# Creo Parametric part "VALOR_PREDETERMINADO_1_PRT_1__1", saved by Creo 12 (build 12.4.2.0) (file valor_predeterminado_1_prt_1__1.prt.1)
Units: Custom; MM, KILOGRAM, SECS

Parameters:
  PTC_WM_ITERATION = "0"
  PTC_WM_VERSION = "-.0"
  PTC_WM_LIFECYCLE_STATE = "In Work"
  PTC_WM_LIFECYCLE = "MO_CADDocument"
  PTC_WM_CREATED_BY = "Maximilian Roepper (Z0017RMS: MO)"
  PTC_WM_CREATED_ON = "18-Sep-26 11:36:42 AM"
  PTC_WM_MODIFIED_BY = "Maximilian Roepper (Z0017RMS: MO)"
  PTC_WM_MODIFIED_ON = "18-Sep-26 11:36:46 AM"
  PDMLINKNUMBER = "PDM000071455242"
  PTC_WM_NAME = "valor_predeterminado_1_prt_1__1.prt"
  PTC_WM_NUMBER = "PDM000071455242"

Other parameters: WEIGHT, WEIGHT_FACTOR, WEIGHT_ADD, _MASS_TEMP, _DIFF_TEMP, MC_ERRORS, SUPPLIER

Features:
  1. coordinate system
  2. datum plane "PRT_YZ"
  3. datum plane "PRT_XY"
  4. datum plane "PRT_XZ"
  5. coordinate system
  6. datum axis
  7. datum axis
  8. datum axis
  9. coordinate system
  10. imported feature
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
Other named items: PRT, SIEMENS_MO, DRW_VIEW_ORG, PRT_X, PRT_Y, PRT_Z, CS0, ROUGH_GROB

Layers: 00_STD_CSYS-KSYS, 01_STD_PLANES-EBENEN, 02_STD_AXES-ACHSEN, 03_STD_CSYS-KSYS, 24_IMPORT_FEAT-IMPORT_KE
